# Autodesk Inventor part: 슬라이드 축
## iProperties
Company: 한국ATC센터
Created: 2012-05
Part Number: 슬라이드 축
Document SubType Name: 모델링
Designer: KYOUNG IL JANG
Mass: 169.556 g
Surface Area: 67.5855 cm^2
Volume: 21.572 cm^3
Density: 7.86 g/cm^3
Material: 강, 연강
변환 표준: STEP AP214IS
파일 이름: C:\Users\SeoGD\Desktop\?쒗뿕\異?stp
전처리기: Build: 253, Release: 2010 SP1 - Date: Wed 07/29/2009
전송 단위: 밀리미터
불확실성: 0.01
Author: KYOUNG IL JANG
